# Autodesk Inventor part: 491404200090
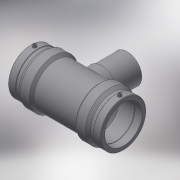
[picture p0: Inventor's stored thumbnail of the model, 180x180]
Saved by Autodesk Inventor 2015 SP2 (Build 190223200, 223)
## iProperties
Created: 2017-06
Part Number: 491404200090
Material: Generic
Description: PLASSON REDUCING TEE 200x90x200
Document SubType Name: Modeling
Designer: KIM
Mass: 8151.33 g
Surface Area: 7097.3 cm^2
Volume: 8151.33 cm^3
Density: 1 g/cm^3
Appearance: Default
Author: KIM
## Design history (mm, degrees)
derived "491404.ipt"
feature "Solid1::491404.ipt"
tag "TaggingFeature1"
body "Solid1"
other parameters: "d0" = 451, "d2" = 261, "d3" = 114, "d4" = 90.2, "d5" = 234.9, "d8" = 168 deg, "d10" = 45.6, "d11" = 15.2, "d13" = 451, "d14" = 17.6296, "d19" = 3.52592, "d20" = 168 deg, "d22" = 242.73, "d23" = 261, "d25" = 135 deg, "d26" = 315.7, "d29" = 125, "d30" = 15, "d31" = 180.4, "d34" = 5 deg, "d35" = 15, "d39" = 5 deg, "d41" = 4, "d42" = 14, "d43" = 0, "d45" = 4, "d46" = 6, "d47" = 0, "d48" = -205, "d51" = 0, "d52" = 72, "d54" = 0, "d55" = 234.9, "d56" = 261, "d57" = 157.85, "d58" = 135 deg, "d59" = 114, "d60" = 114, "d61" = 135 deg, "d62" = 205, "d72" = 205.205, "d73" = 102.6025, "d74" = -205, "d75" = 94.5, "d77" = 0, "d78" = 72, "d80" = 0, "d82" = 74.5, "d83" = 0, "d84" = 3, "d85" = 0, "d86" = 38, "d87" = 237.8754, "d88" = 15.2, "d89" = 3, "d90" = 0, "L_" = 451, "L_1" = 114, "D_" = 261, "A_" = 125, "d_2" = 12, "H_" = 205
